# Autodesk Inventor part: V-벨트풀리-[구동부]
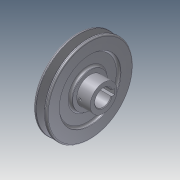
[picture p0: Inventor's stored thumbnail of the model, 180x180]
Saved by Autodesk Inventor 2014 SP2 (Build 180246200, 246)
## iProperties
Company: 한국ATC센터
Created: 2014-10
Part Number: V-벨트풀리-[구동부]
Document SubType Name: Modeling
Designer: 한국ATC센터
Density: 7.86 g/cm^3
Material: 강철, 연강
Mass: 1515.01 g
Surface Area: 468.111 cm^2
Volume: 192.75 cm^3
Appearance: 강철
Author: KYOUNG IL JANG
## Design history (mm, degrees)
sketch "스케치1"
  geometry: L1 (-20, 0)-(20, 0); L2 (-20, 0)-(-20, 26); L3 (-20, 26)-(-16, 26); L4 (-16, 26)-(-16, 46); L5 (-16, 46)-(-20, 46); L6 (-20, 46)-(-20, 64.5); L7 (-20, 64.5)-(-16.062, 64.5); L8 (-16.062, 64.5)-(-12.001, 52); L9 (-12.001, 52)-(-7.999, 52); L10 (-7.999, 52)-(-3.938, 64.5); L11 (-3.938, 64.5)-(0, 64.5); L12 (0, 64.5)-(0, 46); L13 (0, 46)-(-4, 46); L14 (-4, 46)-(-4, 26); L15 (-4, 26)-(0, 26); L16 (0, 26)-(0, 20); L17 (0, 20)-(20, 20); L18 (20, 20)-(20, 0); L19 (-14.6, 60)-(-5.4, 60); 2 further points
  constraints: 38 end point, 11 parallel, 7 collinear, 3 equal length, 3 perpendicular, 2 point on line, 1 coincident, 1 horizontal, 1 midpoint
  dimensions: "d0" = 40 distance of L1.start L1.end; "d1" = 4.5 distance between parallel lines of L7 L19; "d2" = 8 distance between parallel lines of L9 L19; "d3" = 9.2 distance of L19.start L19.end; "d4" = 36 deg angle of L10 L8; "d5" = 20 distance between parallel lines of L12 L6; "d6" = 120 diameter of L19 L1; "d7" = 4 distance of L2.end L3.end; "d8" = 52 diameter of L3 L1; "d9" = 92 diameter of L5 L1; "d10" = 40 diameter of L17 L1
revolve "회전1" sketch "스케치1" stored, may be unused: angle "d11" = 90 deg
sketch "스케치2"
  geometry: L1 (-4, 11.843)-(-4, 16.5); L2 (-4, 16.5)-(4, 16.5); L3 (4, 16.5)-(4, 11.843); A1 r 12.5 centre (0, 0) between (-4, 11.843) and (4, 11.843); 1 further point
  constraints: 6 end point, 2 parallel, 2 point on circle, 1 centre point, 1 coincident, 1 horizontal, 1 vertical
  dimensions: "d12" = 25 diameter of A1; "d13" = 8 distance of L1.end L2.end; "d14" = 29 dimension on A1 L2
extrude "돌출1" cut sketch "스케치2" stored distance "d15" = 10; taper "d16" = 0 deg
chamfer "모따기1" distance "d17" = 1; stored, may be unused: second distance "d18" = 2, angle "d19" = 45 deg
node "작업 평면1"
sketch "스케치3"
  geometry: L1 (10, -20)-(10, 20) reference; 3 further points
  constraints: 1 horizontal alignment, 1 midpoint
  dimensions: "d20" = 15 distance from line of L1 point (-5, 0)
hole "구멍1" sketch "스케치3" at (-5, 0) diameter "d21" = 4.459; stored, may be unused: countersink angle "d25" = 90 deg, drill point angle "d27" = 118 deg; dims "d22" = 6, "d23" = 4, "d24" = 2, "d26" = 8
fillet "모깎기1" dims "d28" = 3, "d29" = 2, "d30" = 0.5, "d31" = 1
node "솔리드1"
